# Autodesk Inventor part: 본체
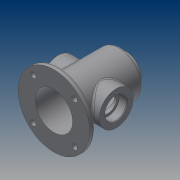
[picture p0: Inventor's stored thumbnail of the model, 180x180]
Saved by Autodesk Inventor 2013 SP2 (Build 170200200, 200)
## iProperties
Created: 2014-12
Part Number: 본체
Material: Generic
Document SubType Name: Modeling
Designer: CADB301
Density: 1 g/cm^3
Author: CADB301
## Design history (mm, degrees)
sketch "스케치1"
  geometry: L1 (-42.5, 25)-(42.5, 25); L2 (42.5, 25)-(42.5, 0); L3 (42.5, 0)-(-42.5, 0); L4 (-42.5, 0)-(-42.5, 25); L5 (-32.5, 49)-(0, 49); L6 (0, 49)-(0, -49); L7 (0, -49)-(-32.5, -49); L8 (-32.5, -49)-(-32.5, 49); L9 (-52.5, -41)-(0, -41); L10 (0, -49)-(-52.5, -49); L11 (-52.5, -49)-(-52.5, -41); 2 further points
  constraints: 22 end point, 5 parallel, 3 horizontal, 2 midpoint, 2 perpendicular, 1 coincident, 1 point on line
  dimensions: "d0" = 85 distance of L1.start L1.end; "d2" = 25 distance of L1.end L2.end; "d3" = 98 distance of L7.end L5.start; "d4" = 32.5 distance of L6.end L7.end; "d7" = 52.5 distance of L6.end L10.end
revolve "회전1" stored, may be unused: angle "d8" = 90 deg
revolve "회전2" stored, may be unused: angle "d9" = 90 deg
hole "구멍1" diameter "d12" = 55; stored, may be unused: countersink angle "d16" = 90 deg, drill point angle "d18" = 0 deg; dims "d10" = 10, "d11" = 10, "d13" = 6, "d14" = 4, "d15" = 2, "d17" = 93
node "작업 평면1"
sketch "스케치2"
  geometry: C1 r 22.5 at (0, 0); 1 further point
  constraints: 1 centre point, 1 coincident
  dimensions: "d20" = 45 diameter of C1
extrude "돌출1" join sketch "스케치2" stored distance "d21" = 10; taper "d22" = 0 deg
hole "구멍2" diameter "d25" = 27; stored, may be unused: countersink angle "d29" = 90 deg, drill point angle "d31" = 0 deg; dims "d23" = 10, "d24" = 10, "d26" = 6, "d27" = 4, "d28" = 2, "d30" = 93
sketch "스케치3"
  geometry: 2 further points
  constraints: 1 vertical alignment
  dimensions: "d41" = 17.5 distance of point (0, 0) point (0, 17.5)
hole "구멍4" sketch "스케치3" at (0, 17.5) diameter "d42" = 2.459; stored, may be unused: countersink angle "d46" = 90 deg, drill point angle "d48" = 118 deg; dims "d43" = 6, "d44" = 4, "d45" = 2, "d47" = 8
sketch "스케치4"
  geometry: 2 further points
  constraints: 1 vertical alignment
  dimensions: "d52" = 20.5 distance of point (0, 0) point (0, 20.5)
hole "구멍5" sketch "스케치4" at (0, 20.5) diameter "d53" = 2.459; stored, may be unused: countersink angle "d57" = 90 deg, drill point angle "d59" = 118 deg; dims "d54" = 6, "d55" = 4, "d56" = 2, "d58" = 8
sketch "스케치5"
  geometry: C1 r 16 at (0, 0); 2 further points
  constraints: 1 centre point, 1 coincident, 1 vertical alignment
  dimensions: "d63" = 32 diameter of C1; "d64" = 20.5 distance of C1.centre point (0, 20.5)
extrude "돌출2" cut sketch "스케치5" distance "d65" = 12; taper "d66" = 0 deg
hole "구멍6" sketch "스케치5" diameter "d67" = 2.459; stored, may be unused: countersink angle "d71" = 90 deg, drill point angle "d73" = 118 deg; dims "d68" = 6, "d69" = 4, "d70" = 2, "d72" = 8
hole "구멍7" diameter "d79" = 25; stored, may be unused: countersink angle "d83" = 90 deg, drill point angle "d85" = 0 deg; dims "d77" = 10, "d78" = 10, "d80" = 6, "d81" = 4, "d82" = 2, "d84" = 8
chamfer "모따기1" distance "d86" = 1; stored, may be unused: second distance "d87" = 2, angle "d88" = 45 deg
fillet "모깎기1" dims "d89" = 3
fillet "모깎기2" dims "d90" = 0.3
sketch "스케치6" dims "d92" = 86
  geometry: L1 (0, 0)-(42.726, 42.726); L2 (0, 0)-(60.424, 0); 2 further points
  constraints: 4 end point, 1 coincident, 1 equal length, 1 horizontal, 1 point on line, 3 other
  dimensions: "d91" = 45 deg angle of L2 L1
hole "구멍8" sketch "스케치6" at (30.406, 30.406) diameter "d93" = 8; stored, may be unused: countersink angle "d97" = 90 deg, drill point angle "d99" = 0 deg; dims "d94" = 6, "d95" = 4, "d96" = 2, "d98" = 8
node "작업 평면2"
sketch "스케치8"
  geometry: L1 (49, 27.5)-(49, -27.5) reference; 2 further points
  constraints: 1 horizontal alignment, 1 other
  dimensions: "d105" = 89 distance from line of L1 point (-40, 0)
feature "엠보싱1" sketch "스케치8" dims "d0" = 85, "d2" = 25, "d3" = 98, "d4" = 32.5, "d7" = 52.5, "d19" = -106, "d106" = 1, "d107" = 0
node "솔리드1"
pattern_circular "원형 패턴1" dims angle "d50" = 360 deg
pattern_circular "원형 패턴3" dims angle "d75" = 360 deg
mirror "대칭3"
pattern_circular "원형 패턴4" dims angle "d101" = 360 deg
other parameters: "d103" = -32.5
